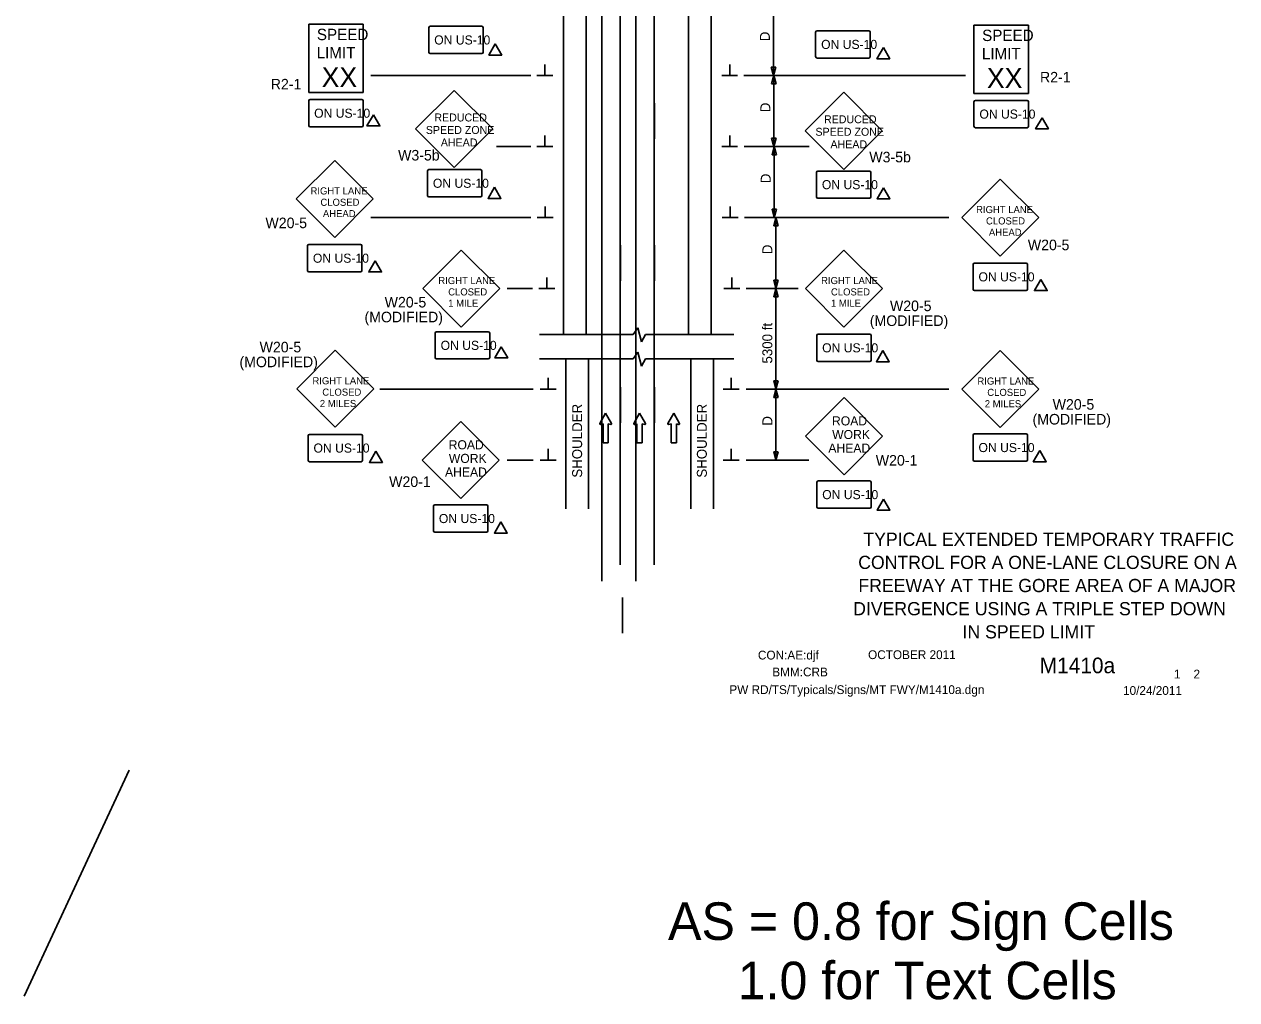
# Model space of a CAD drawing. Extents: x 16574 to 18479, y 5718 to 6974.
# Drawn here: x 16574 to 17428, y 5718 to 6405 of the extents above; entities that cross this region are included whole.
import ezdxf

# ---------------------------------------------------------------- set-up
doc = ezdxf.new("R2010")
doc.units = 0
for name, color, linetype in [('ALI_LEGAL_EX', 7, 'Continuous'), ('BORDER', 7, 'Continuous'), ('BORDER_SIGNAL_WO', 7, 'Continuous'), ('MT_SCRATCH_LEVEL_E', 7, 'Continuous'), ('PAVT_EDGE_EX', 7, 'Continuous'), ('TRAFFIC_SIGNS_PR', 7, 'Continuous'), ('TYPICAL_TEXT_DIMEN_PR', 7, 'Continuous')]:
    doc.layers.add(name, color=color, linetype=linetype)

msp = doc.modelspace()

# ---------------------------------------------------------------- linework, layer by layer
at = {"layer": 'ALI_LEGAL_EX'}
for p, q in [((16980.68, 6974.12), (16980.68, 6155.98)), ((17004.68, 6974.12), (17004.68, 6155.98)), ((16980.68, 6877.04), (16980.68, 6013.12)), ((17004.68, 6877.04), (17004.68, 6013.12)), ((16993.65, 6024.8), (16993.65, 6525.15)), ((17017.65, 6024.8), (17017.65, 6525.15))]:
    msp.add_line(p, q, dxfattribs=at)
for points in [[(16993.7, 6324.8), (16993.7, 6349.8)], [(17017.7, 6324.8), (17017.7, 6349.8)], [(16993.75, 6224.79), (16993.75, 6249.79)], [(17017.75, 6224.79), (17017.75, 6249.79)], [(16993.8, 6124.79), (16993.8, 6149.79)], [(17017.8, 6124.79), (17017.8, 6149.79)], [(16995.37, 6001.71), (16995.37, 5976.71)]]:
    msp.add_lwpolyline(points, dxfattribs=at)
at = {"layer": 'MT_SCRATCH_LEVEL_E'}
for p, q in [((16983.38, 6131.58), (16979.27, 6124.34)), ((16987.53, 6124.34), (16983.38, 6131.58)), ((17007.29, 6131.58), (17003.18, 6124.34)), ((17011.44, 6124.34), (17007.29, 6131.58)), ((17031.34, 6131.58), (17027.23, 6124.34)), ((17035.49, 6124.34), (17031.34, 6131.58)), ((16979.76, 6123.66), (16981.53, 6123.97)), ((16981.53, 6123.97), (16981.53, 6110.72)), ((16985.27, 6110.72), (16985.27, 6123.97)), ((16985.27, 6123.97), (16987.05, 6123.66)), ((17003.66, 6123.66), (17005.44, 6123.97)), ((17005.44, 6123.97), (17005.44, 6110.72)), ((17009.18, 6110.72), (17009.18, 6123.97)), ((17009.18, 6123.97), (17010.96, 6123.66)), ((17027.71, 6123.66), (17029.49, 6123.97)), ((17029.49, 6123.97), (17029.49, 6110.72)), ((17033.23, 6110.72), (17033.23, 6123.97)), ((17033.23, 6123.97), (17035.01, 6123.66)), ((16981.53, 6110.72), (16985.27, 6110.72)), ((17005.44, 6110.72), (17009.18, 6110.72)), ((17029.49, 6110.72), (17033.23, 6110.72))]:
    msp.add_line(p, q, dxfattribs=at)
for centre, start, end in [((16979.68, 6124.12), 150.42484, 279.96381), ((16987.12, 6124.12), 260.03619, 29.77312), ((17003.58, 6124.12), 150.42484, 279.96381), ((17011.03, 6124.12), 260.03619, 29.77312), ((17027.64, 6124.12), 150.42484, 279.96381), ((17035.08, 6124.12), 260.03619, 29.77312)]:
    msp.add_arc(centre, 0.463, start, end, dxfattribs=at)
at = {"layer": 'PAVT_EDGE_EX'}
for p, q in [((16953.65, 6525.15), (16953.65, 6186.91)), ((16969.65, 6525.15), (16969.65, 6186.91)), ((17041.65, 6525.15), (17041.65, 6186.91)), ((17057.65, 6525.15), (17057.65, 6186.91)), ((16955.37, 6169.77), (16955.37, 6064.1)), ((16971.37, 6169.77), (16971.37, 6064.1)), ((17043.37, 6169.77), (17043.37, 6064.1)), ((17059.37, 6169.77), (17059.37, 6064.1))]:
    msp.add_line(p, q, dxfattribs=at)
at = {"layer": 'TRAFFIC_SIGNS_PR'}
for p, q in [((16774.16, 6405.45), (16812.56, 6405.45)), ((16774.16, 6357.45), (16774.16, 6405.45)), ((16812.56, 6357.45), (16812.56, 6405.45)), ((16858.76, 6403.04), (16858.76, 6385.84)), ((16859.76, 6404.04), (16896.17, 6404.04)), ((16897.17, 6403.04), (16897.17, 6385.84)), ((17131.36, 6399.9), (17131.36, 6382.7)), ((17132.36, 6400.9), (17168.77, 6400.9)), ((17169.77, 6399.9), (17169.77, 6382.7)), ((17242.89, 6404.82), (17281.29, 6404.82)), ((17242.89, 6356.82), (17242.89, 6404.82)), ((17281.29, 6356.82), (17281.29, 6404.82)), ((16859.76, 6384.84), (16896.17, 6384.84)), ((17132.36, 6381.7), (17168.77, 6381.7)), ((16774.16, 6357.45), (16812.56, 6357.45)), ((16876.66, 6358.89), (16849.51, 6331.73)), ((16903.81, 6331.73), (16876.66, 6358.89)), ((17151.18, 6357.6), (17124.03, 6330.44)), ((17178.33, 6330.44), (17151.18, 6357.6)), ((17242.89, 6356.82), (17281.29, 6356.82)), ((16774.16, 6351.45), (16774.16, 6334.25)), ((16775.16, 6352.45), (16811.56, 6352.45)), ((16812.56, 6351.45), (16812.56, 6334.25)), ((17242.89, 6350.82), (17242.89, 6333.62)), ((17243.89, 6351.82), (17280.29, 6351.82)), ((17281.29, 6350.82), (17281.29, 6333.62)), ((16775.16, 6333.25), (16811.56, 6333.25)), ((16849.51, 6331.73), (16876.66, 6304.58)), ((16876.66, 6304.58), (16903.81, 6331.73)), ((17124.03, 6330.44), (17151.18, 6303.29)), ((17151.18, 6303.29), (17178.33, 6330.44)), ((17243.89, 6332.62), (17280.29, 6332.62)), ((16792.5, 6309.62), (16765.35, 6282.47)), ((16819.65, 6282.47), (16792.5, 6309.62)), ((16857.83, 6302.11), (16857.83, 6284.91)), ((16858.83, 6303.11), (16895.23, 6303.11)), ((16896.23, 6302.11), (16896.23, 6284.91)), ((17131.91, 6301.13), (17131.91, 6283.93)), ((17132.91, 6302.13), (17169.31, 6302.13)), ((17170.31, 6301.13), (17170.31, 6283.93)), ((17261.44, 6296.48), (17234.29, 6269.33)), ((17288.59, 6269.33), (17261.44, 6296.48)), ((16765.35, 6282.47), (16792.5, 6255.32)), ((16792.5, 6255.32), (16819.65, 6282.47)), ((16858.83, 6283.91), (16895.23, 6283.91)), ((17132.91, 6282.93), (17169.31, 6282.93)), ((17234.29, 6269.33), (17261.44, 6242.18)), ((17261.44, 6242.18), (17288.59, 6269.33)), ((16773.3, 6249.32), (16773.3, 6232.12)), ((16774.3, 6250.32), (16810.7, 6250.32)), ((16811.7, 6249.32), (16811.7, 6232.12)), ((16881.62, 6246.48), (16854.47, 6219.33)), ((16908.77, 6219.33), (16881.62, 6246.48)), ((17151.3, 6246.48), (17124.15, 6219.33)), ((17178.45, 6219.33), (17151.3, 6246.48)), ((17243.24, 6237.18), (17279.65, 6237.18)), ((16774.3, 6231.12), (16810.7, 6231.12)), ((17242.24, 6236.18), (17242.24, 6218.98)), ((17280.65, 6236.18), (17280.65, 6218.98)), ((16854.47, 6219.33), (16881.62, 6192.18)), ((16881.62, 6192.18), (16908.77, 6219.33)), ((17124.15, 6219.33), (17151.3, 6192.18)), ((17151.3, 6192.18), (17178.45, 6219.33)), ((17243.24, 6217.98), (17279.65, 6217.98)), ((16863.29, 6187.92), (16863.29, 6170.72)), ((16864.29, 6188.92), (16900.69, 6188.92)), ((16901.69, 6187.92), (16901.69, 6170.72)), ((17132.1, 6186.18), (17132.1, 6168.98)), ((17133.1, 6187.18), (17169.5, 6187.18)), ((17170.5, 6186.18), (17170.5, 6168.98)), ((16792.92, 6175.89), (16765.77, 6148.74)), ((16820.07, 6148.74), (16792.92, 6175.89)), ((16864.29, 6169.72), (16900.69, 6169.72)), ((17133.1, 6167.98), (17169.5, 6167.98)), ((17261.45, 6175.7), (17234.29, 6148.55)), ((17288.6, 6148.55), (17261.45, 6175.7)), ((16765.77, 6148.74), (16792.92, 6121.59)), ((16792.92, 6121.59), (16820.07, 6148.74)), ((17151.34, 6142.55), (17124.18, 6115.4)), ((17178.5, 6115.4), (17151.34, 6142.55)), ((17234.29, 6148.55), (17261.45, 6121.4)), ((17261.45, 6121.4), (17288.6, 6148.55)), ((16881.26, 6125.71), (16854.1, 6098.55)), ((16908.41, 6098.55), (16881.26, 6125.71)), ((17243.25, 6116.95), (17279.65, 6116.95)), ((16773.72, 6115.59), (16773.72, 6098.39)), ((16774.72, 6116.59), (16811.12, 6116.59)), ((16812.12, 6115.59), (16812.12, 6098.39)), ((17124.18, 6115.4), (17151.34, 6088.24)), ((17151.34, 6088.24), (17178.5, 6115.4)), ((17242.25, 6115.95), (17242.25, 6098.75)), ((17280.65, 6115.95), (17280.65, 6098.75)), ((16774.72, 6097.39), (16811.12, 6097.39)), ((16854.1, 6098.55), (16881.26, 6071.4)), ((16881.26, 6071.4), (16908.41, 6098.55)), ((17243.25, 6097.75), (17279.65, 6097.75)), ((17132.14, 6082.8), (17132.14, 6065.59)), ((17133.14, 6083.8), (17169.54, 6083.8)), ((17170.54, 6082.8), (17170.54, 6065.59)), ((16862.06, 6065.95), (16862.06, 6048.75)), ((16863.06, 6066.95), (16899.46, 6066.95)), ((16900.46, 6065.95), (16900.46, 6048.75)), ((17133.14, 6064.59), (17169.54, 6064.59)), ((16863.06, 6047.75), (16899.46, 6047.75))]:
    msp.add_line(p, q, dxfattribs=at)
for centre, start, end in [((16859.77, 6403.04), 90, 180), ((16896.17, 6403.04), 0, 90), ((17132.36, 6399.9), 90, 180), ((17168.77, 6399.9), 0, 90), ((16859.77, 6385.84), 180, 270), ((16896.17, 6385.84), 270, 0), ((17132.36, 6382.7), 180, 270), ((17168.77, 6382.7), 270, 0), ((16775.16, 6351.45), 90, 180), ((16811.56, 6351.45), 0, 90), ((17243.89, 6350.82), 90, 180), ((17280.29, 6350.82), 0, 90), ((16775.16, 6334.25), 180, 270), ((16811.56, 6334.25), 270, 0), ((17243.89, 6333.62), 180, 270), ((17280.29, 6333.62), 270, 0), ((16858.83, 6302.11), 90, 180), ((16895.23, 6302.11), 0, 90), ((17132.91, 6301.13), 90, 180), ((17169.31, 6301.13), 0, 90), ((16858.83, 6284.91), 180, 270), ((16895.23, 6284.91), 270, 0), ((17132.91, 6283.93), 180, 270), ((17169.31, 6283.93), 270, 0), ((16774.3, 6249.32), 90, 180), ((16810.7, 6249.32), 0, 90), ((17243.24, 6236.18), 90, 180), ((17279.65, 6236.18), 0, 90), ((16774.3, 6232.12), 180, 270), ((16810.7, 6232.12), 270, 0), ((17243.24, 6218.98), 180, 270), ((17279.65, 6218.98), 270, 0), ((16864.29, 6187.92), 90, 180), ((16900.69, 6187.92), 0, 90), ((17133.1, 6186.18), 90, 180), ((17169.5, 6186.18), 0, 90), ((16864.29, 6170.72), 180, 270), ((16900.69, 6170.72), 270, 0), ((17133.1, 6168.98), 180, 270), ((17169.5, 6168.98), 270, 0), ((17243.25, 6115.95), 90, 180), ((17279.65, 6115.95), 0, 90), ((16774.72, 6115.59), 90, 180), ((16811.12, 6115.59), 0, 90), ((16774.72, 6098.39), 180, 270), ((16811.12, 6098.39), 270, 0), ((17243.25, 6098.75), 180, 270), ((17279.65, 6098.75), 270, 0), ((17133.14, 6082.8), 90, 180), ((17169.54, 6082.8), 0, 90), ((16863.06, 6065.95), 90, 180), ((16899.46, 6065.95), 0, 90), ((17133.14, 6065.59), 180, 270), ((17169.54, 6065.59), 270, 0), ((16863.06, 6048.75), 180, 270), ((16899.46, 6048.75), 270, 0)]:
    msp.add_arc(centre, 1, start, end, dxfattribs=at)
at = {"layer": 'TYPICAL_TEXT_DIMEN_PR'}
for p, q in [((17101.65, 6419.33), (17101.65, 6369.33)), ((16940.52, 6369.33), (16940.52, 6377.11)), ((17070.77, 6369.33), (17070.77, 6377.11)), ((17101.65, 6369.33), (17100.08, 6375.19)), ((17100.08, 6375.19), (17101.65, 6375.19)), ((17101.65, 6375.19), (17103.22, 6375.19)), ((17103.22, 6375.19), (17101.65, 6369.33)), ((16930.65, 6369.33), (16817.92, 6369.33)), ((16934.9, 6369.33), (16946.15, 6369.33)), ((17076.4, 6369.33), (17065.15, 6369.33)), ((17080.65, 6369.33), (17237.03, 6369.33)), ((17100.36, 6363.47), (17101.93, 6369.33)), ((17101.93, 6369.33), (17101.93, 6319.33)), ((17101.93, 6369.33), (17103.51, 6363.47)), ((17101.93, 6363.47), (17100.36, 6363.47)), ((17103.51, 6363.47), (17101.93, 6363.47)), ((16940.52, 6319.33), (16940.52, 6327.11)), ((17070.77, 6319.33), (17070.77, 6327.11)), ((17101.93, 6319.33), (17100.36, 6325.19)), ((17100.36, 6325.19), (17101.93, 6325.19)), ((17101.93, 6325.19), (17103.51, 6325.19)), ((17103.51, 6325.19), (17101.93, 6319.33)), ((16930.65, 6319.33), (16906.38, 6319.33)), ((16934.9, 6319.33), (16946.15, 6319.33)), ((17076.4, 6319.33), (17065.15, 6319.33)), ((17080.93, 6319.33), (17126.78, 6319.33)), ((17100.65, 6313.47), (17102.22, 6319.33)), ((17102.22, 6313.47), (17100.65, 6313.47)), ((17102.22, 6319.33), (17102.22, 6269.33)), ((17102.22, 6319.33), (17103.79, 6313.47)), ((17103.79, 6313.47), (17102.22, 6313.47)), ((16940.81, 6269.33), (16940.81, 6277.11)), ((17071.06, 6269.33), (17071.06, 6277.11)), ((17102.22, 6269.33), (17100.65, 6275.19)), ((17100.65, 6275.19), (17102.22, 6275.19)), ((17102.22, 6275.19), (17103.79, 6275.19)), ((17103.79, 6275.19), (17102.22, 6269.33)), ((16930.65, 6269.33), (16817.92, 6269.33)), ((16935.18, 6269.33), (16946.43, 6269.33)), ((17076.68, 6269.33), (17065.43, 6269.33)), ((17081.22, 6269.33), (17225.24, 6269.33)), ((17101.8, 6263.47), (17103.37, 6269.33)), ((17103.37, 6263.47), (17101.8, 6263.47)), ((17103.37, 6269.33), (17103.37, 6219.33)), ((17103.37, 6269.33), (17104.94, 6263.47)), ((17104.94, 6263.47), (17103.37, 6263.47)), ((16931.8, 6219.33), (16913.93, 6219.33)), ((16936.33, 6219.33), (16947.58, 6219.33)), ((16941.96, 6219.33), (16941.96, 6227.11)), ((17077.83, 6219.33), (17066.58, 6219.33)), ((17072.21, 6219.33), (17072.21, 6227.11)), ((17082.37, 6219.33), (17119, 6219.33)), ((17103.37, 6219.33), (17101.8, 6225.19)), ((17101.8, 6225.19), (17103.37, 6225.19)), ((17101.8, 6213.47), (17103.37, 6219.33)), ((17103.37, 6225.19), (17104.94, 6225.19)), ((17104.94, 6225.19), (17103.37, 6219.33)), ((17103.37, 6219.33), (17103.37, 6148.55)), ((17103.37, 6219.33), (17104.94, 6213.47)), ((17103.37, 6213.47), (17101.8, 6213.47)), ((17104.94, 6213.47), (17103.37, 6213.47)), ((17002.72, 6186.91), (16936.78, 6186.91)), ((17005.97, 6191.71), (17002.72, 6186.91)), ((17008.71, 6181.77), (17005.97, 6191.71)), ((17011.46, 6186.91), (17008.71, 6181.77)), ((17073.79, 6186.91), (17011.46, 6186.91)), ((17002.72, 6169.77), (16936.78, 6169.77)), ((17005.97, 6174.57), (17002.72, 6169.77)), ((17008.71, 6164.63), (17005.97, 6174.57)), ((17011.46, 6169.77), (17008.71, 6164.63)), ((17073.79, 6169.77), (17011.46, 6169.77)), ((16942.99, 6148.55), (16942.99, 6156.34)), ((17071.74, 6148.55), (17071.74, 6156.34)), ((17103.37, 6148.55), (17101.8, 6154.41)), ((17101.8, 6154.41), (17103.37, 6154.41)), ((17103.37, 6154.41), (17104.94, 6154.41)), ((17104.94, 6154.41), (17103.37, 6148.55)), ((16824.35, 6148.55), (16932.37, 6148.55)), ((16937.37, 6148.55), (16948.62, 6148.55)), ((17077.37, 6148.55), (17066.12, 6148.55)), ((17225.24, 6148.55), (17082.37, 6148.55)), ((17101.8, 6142.69), (17103.37, 6148.55)), ((17103.37, 6142.69), (17101.8, 6142.69)), ((17103.37, 6148.55), (17103.37, 6098.55)), ((17103.37, 6148.55), (17104.94, 6142.69)), ((17104.94, 6142.69), (17103.37, 6142.69)), ((16942.99, 6098.55), (16942.99, 6106.34)), ((17071.74, 6098.55), (17071.74, 6106.34)), ((17103.37, 6098.55), (17101.8, 6104.41)), ((17101.8, 6104.41), (17103.37, 6104.41)), ((17103.37, 6104.41), (17104.94, 6104.41)), ((17104.94, 6104.41), (17103.37, 6098.55)), ((16932.37, 6098.55), (16913.93, 6098.55)), ((16948.62, 6098.55), (16937.37, 6098.55)), ((17077.37, 6098.55), (17066.12, 6098.55)), ((17126.46, 6098.55), (17082.37, 6098.55)), ((16647.75, 5880), (16573.76, 5720.95))]:
    msp.add_line(p, q, dxfattribs=at)
for points in [[(16905.66, 6391.63), (16901.14, 6383.79), (16910.19, 6383.79)], [(17179.06, 6389.08), (17174.54, 6381.25), (17183.59, 6381.25)], [(16819.76, 6341.69), (16815.24, 6333.86), (16824.29, 6333.86)], [(17290.84, 6339.69), (17286.31, 6331.85), (17295.36, 6331.85)], [(16905.05, 6290.7), (16900.52, 6282.86), (16909.58, 6282.86)], [(17179.11, 6290.38), (17174.58, 6282.55), (17183.64, 6282.55)], [(16821.01, 6238.89), (16816.48, 6231.06), (16825.53, 6231.06)], [(17289.95, 6225.75), (17285.43, 6217.92), (17294.48, 6217.92)], [(16909.86, 6178.29), (16905.33, 6170.45), (16914.38, 6170.45)], [(17178.65, 6175.62), (17174.13, 6167.79), (17183.18, 6167.79)], [(16821.53, 6104.73), (16817, 6096.89), (16826.05, 6096.89)], [(17289.25, 6105.21), (17284.72, 6097.38), (17293.78, 6097.38)], [(17179.14, 6071.1), (17174.61, 6063.26), (17183.66, 6063.26)], [(16909.51, 6054.95), (16904.99, 6047.12), (16914.04, 6047.12)]]:
    msp.add_lwpolyline(points, close=True, dxfattribs=at)

# ---------------------------------------------------------------- texts
at = {"layer": 'BORDER'}
for s, p in [('TYPICAL EXTENDED TEMPORARY TRAFFIC', (17164.97, 6038.11)), ('CONTROL FOR A ONE-LANE CLOSURE ON A', (17161.34, 6021.81)), ('FREEWAY AT THE GORE AREA OF A MAJOR', (17161.47, 6005.51)), (' DIVERGENCE USING A TRIPLE STEP DOWN ', (17154.34, 5989.2)), ('IN SPEED LIMIT', (17234.84, 5972.9))]:
    msp.add_text(s, height=9.3, dxfattribs=at).set_placement(p)
at = {"layer": 'BORDER_SIGNAL_WO'}
for s, height, p in [('CON:AE:djf  ', 6.2, (17090.69, 5958.06)), ('    OCTOBER 2011    ', 6.2, (17159.08, 5958.34)), ('    M1410a   ', 11, (17272.86, 5948.38)), ('BMM:CRB   ', 6.2, (17100.81, 5946.17)), (' 1    2 ', 6.2, (17381.45, 5944.7)), ('PW RD/TS/Typicals/Signs/MT FWY/M1410a.dgn      ', 6.2, (17070.55, 5933.71)), ('10/24/2011    ', 6.2, (17347.93, 5933.13)), ('AS = 0.8 for Sign Cells', 26.4241, (17027.34, 5760.56)), ('     1.0 for Text Cells', 26.4241, (17027.34, 5718.77))]:
    msp.add_text(s, height=height, dxfattribs=at).set_placement(p)
at = {"layer": 'TRAFFIC_SIGNS_PR'}
for s, height, p in [('SPEED', 8, (16779.93, 6394.31)), ('SPEED', 8, (17248.66, 6393.68)), ('ON US-10', 6.401, (16862.61, 6391.24)), ('ON US-10', 6.401, (17135.2, 6388.1)), ('LIMIT', 8, (16779.77, 6381.51)), ('LIMIT', 8, (17248.49, 6380.88)), ('XX', 14.031, (16783.28, 6361.21)), ('XX', 14.031, (17252, 6360.58)), ('R2-1', 7.44, (16747.43, 6359.58)), ('R2-1', 7.44, (17289.43, 6364.5)), ('ON US-10', 6.4, (16778, 6339.65)), ('REDUCED', 5.6, (16862.72, 6337.04)), ('REDUCED', 5.6, (17137.24, 6335.75)), ('ON US-10', 6.4, (17246.73, 6339.02)), ('SPEED ZONE', 5.6, (16856.71, 6328.24)), ('SPEED ZONE', 5.6, (17131.23, 6326.95)), ('AHEAD', 5.6, (16867.27, 6319.44)), ('AHEAD', 5.6, (17141.79, 6318.15)), ('W3-5b', 7.44, (16837.14, 6309.53)), ('W3-5b', 7.44, (17169.14, 6308.23)), ('ON US-10', 6.4, (16861.67, 6290.31)), ('RIGHT LANE', 4.999, (16775.45, 6285.62)), ('ON US-10', 6.4, (17135.75, 6289.33)), ('CLOSED', 4.999, (16782.43, 6277.62)), ('AHEAD', 4.999, (16784.18, 6269.62)), ('RIGHT LANE', 4.999, (17244.39, 6272.48)), ('W20-5', 7.439, (16743.7, 6261.86)), ('CLOSED', 4.999, (17251.37, 6264.48)), ('AHEAD', 4.999, (17253.43, 6256.49)), ('W20-5', 7.439, (17280.84, 6246.34)), ('ON US-10', 6.401, (16777.14, 6237.52)), ('ON US-10', 6.401, (17246.08, 6224.38)), ('RIGHT LANE', 4.999, (16865.5, 6222.48)), ('CLOSED', 4.999, (16872.45, 6214.48)), ('RIGHT LANE', 4.999, (17135.18, 6222.48)), ('CLOSED', 4.999, (17142.14, 6214.49)), ('W20-5', 7.439, (16827.68, 6206.01)), ('1 MILE', 4.999, (16872.45, 6206.48)), ('1 MILE', 4.999, (17142.13, 6206.49)), ('W20-5', 7.439, (17183.69, 6203.42)), ('(MODIFIED)', 7.439, (16813.5, 6195.57)), ('(MODIFIED)', 7.439, (17169.51, 6192.98)), ('W20-5', 7.439, (16739.58, 6174.39)), ('ON US-10', 6.401, (16867.12, 6176.12)), ('ON US-10', 6.401, (17135.93, 6174.38)), ('(MODIFIED)', 7.439, (16725.4, 6163.95)), ('RIGHT LANE', 4.999, (16776.8, 6151.89)), ('RIGHT LANE', 4.999, (17245.33, 6151.7)), ('CLOSED', 4.999, (16783.76, 6143.89)), ('CLOSED', 4.999, (17252.28, 6143.7)), ('2 MILES', 4.999, (16782.01, 6135.89)), ('2 MILES', 4.999, (17250.53, 6135.71)), ('W20-5', 7.439, (17298.34, 6134.01)), ('ROAD', 6.401, (17142.88, 6122.93)), ('(MODIFIED)', 7.439, (17284.16, 6123.57)), ('WORK', 6.401, (17142.99, 6113.33)), ('ON US-10', 6.401, (16777.56, 6103.79)), ('ROAD', 6.401, (16872.8, 6106.09)), ('AHEAD', 6.401, (17140.3, 6103.73)), ('ON US-10', 6.401, (17246.09, 6104.15)), ('WORK', 6.401, (16872.91, 6096.49)), ('W20-1', 7.441, (17173.69, 6094.63)), ('AHEAD', 6.401, (16870.22, 6086.89)), ('W20-1', 7.441, (16830.84, 6079.56)), ('ON US-10', 6.401, (17135.98, 6071)), ('ON US-10', 6.401, (16865.89, 6054.15))]:
    msp.add_text(s, height=height, dxfattribs=at).set_placement(p)
at = {"layer": 'TYPICAL_TEXT_DIMEN_PR'}
for s, p in [('D', (17099.09, 6393.55)), ('D', (17099.38, 6343.55)), ('D', (17099.66, 6293.55)), ('D', (17100.81, 6243.55)), ('5300 ft', (17100.81, 6166.51)), ('SHOULDER', (16966.81, 6086.13)), ('SHOULDER', (17054.67, 6086.13)), ('D', (17100.81, 6122.77))]:
    msp.add_text(s, height=7, rotation=90, dxfattribs=at).set_placement(p)

doc.saveas('drawing.dxf')
